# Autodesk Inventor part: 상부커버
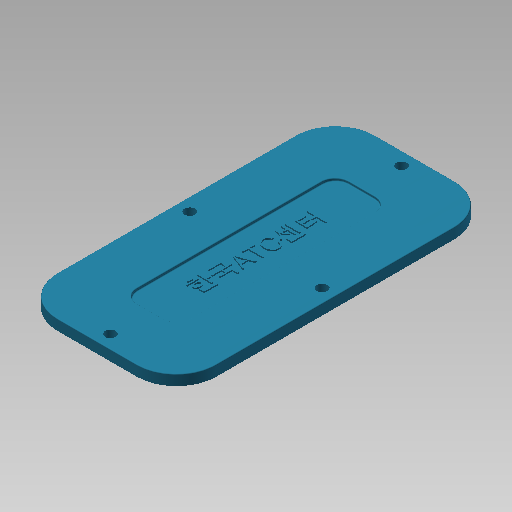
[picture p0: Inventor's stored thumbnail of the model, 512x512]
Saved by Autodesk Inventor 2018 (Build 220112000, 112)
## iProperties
Created: 2016-02
Part Number: 상부커버
Material: 강철, 연강
Document SubType Name: Modeling
Designer: mduedu
Density: 1 g/cm^3
Mass: 15.5198 g
Surface Area: 149.263 cm^2
Volume: 15.5198 cm^3
Appearance: 터키옥색
Author: mduedu
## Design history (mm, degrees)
sketch "스케치1"
  geometry: L1 (30, 60)-(-30, 60); L2 (-30, 60)-(-30, -60); L3 (-30, -60)-(30, -60); L4 (30, -60)-(30, 60); L5 (30, 60)-(-30, -60); L6 (-30, 60)-(30, -60); 1 further point
  constraints: 12 end point, 2 midpoint, 2 parallel, 1 horizontal, 1 perpendicular
  dimensions: "d0" = 60 distance of L2.end L3.end; "d2" = 120 distance of L1.end L2.end
extrude "돌출1" new body sketch "스케치1" distance "d3" = 4; taper "d4" = 0 deg
fillet "모깎기1" dims "d5" = 15
sketch "스케치2"
  geometry: L1 (30, 45)-(30, -45) reference; L2 (15, -60)-(-15, -60) reference; L3 (-30, -45)-(-30, 45) reference; L4 (-15, 60)-(15, 60) reference; L5 (25, 45)-(25, -45); L6 (15, -55)-(-15, -55); L7 (-25, -45)-(-25, 45); L8 (-15, 55)-(15, 55); A1 r 15 centre (15, 45) between (30, 45) and (15, 60) reference; A2 r 15 centre (15, -45) between (15, -60) and (30, -45) reference; A3 r 15 centre (-15, -45) between (-30, -45) and (-15, -60) reference; A4 r 15 centre (-15, 45) between (-15, 60) and (-30, 45) reference; A5 r 10 centre (15, 45) between (25, 45) and (15, 55); A6 r 10 centre (15, -45) between (15, -55) and (25, -45); A7 r 10 centre (-15, -45) between (-25, -45) and (-15, -55); A8 r 10 centre (-15, 45) between (-15, 55) and (-25, 45); 4 further points
  constraints: 8 end point, 8 point on circle, 4 centre point, 4 midpoint, 7 other
  dimensions: "d8" = 5 distance between parallel lines of L7 L3
hole "구멍1" sketch "스케치2" at (0, 55), (25, 0), (0, -55), (-25, 0) diameter "d9" = 4; stored, may be unused: countersink angle "d13" = 90 deg, drill point angle "d15" = 118 deg; dims "d10" = 6, "d11" = 4, "d12" = 2, "d14" = 8
sketch "스케치3"
  geometry: L1 (10, -40)-(-10, -40); L2 (-10, -40)-(-10, 40); L3 (-10, 40)-(10, 40); L4 (10, 40)-(10, -40); L5 (10, -40)-(-10, 40); L6 (-10, -40)-(10, 40); 1 further point
  constraints: 12 end point, 2 midpoint, 2 parallel, 1 horizontal, 1 perpendicular
  dimensions: "d16" = 80 distance of L1.end L2.end; "d18" = 20 distance of L2.end L3.end
extrude "돌출2" cut sketch "스케치3" distance "d19" = 1; taper "d20" = 0 deg
fillet "모깎기2" dims "d21" = 5
fillet "모깎기3" dims "d22" = 0.3
fillet "모깎기4" dims "d23" = 0.3
sketch "스케치4"
  geometry: 2 further points
  constraints: 1 coincident, 1 other
feature "엠보싱1" sketch "스케치4" dims "d0" = 60, "d2" = 120, "d11" = 4, "d24" = 0.5, "d25" = 0
node "솔리드1"
node "절단 모서리 투영1"
